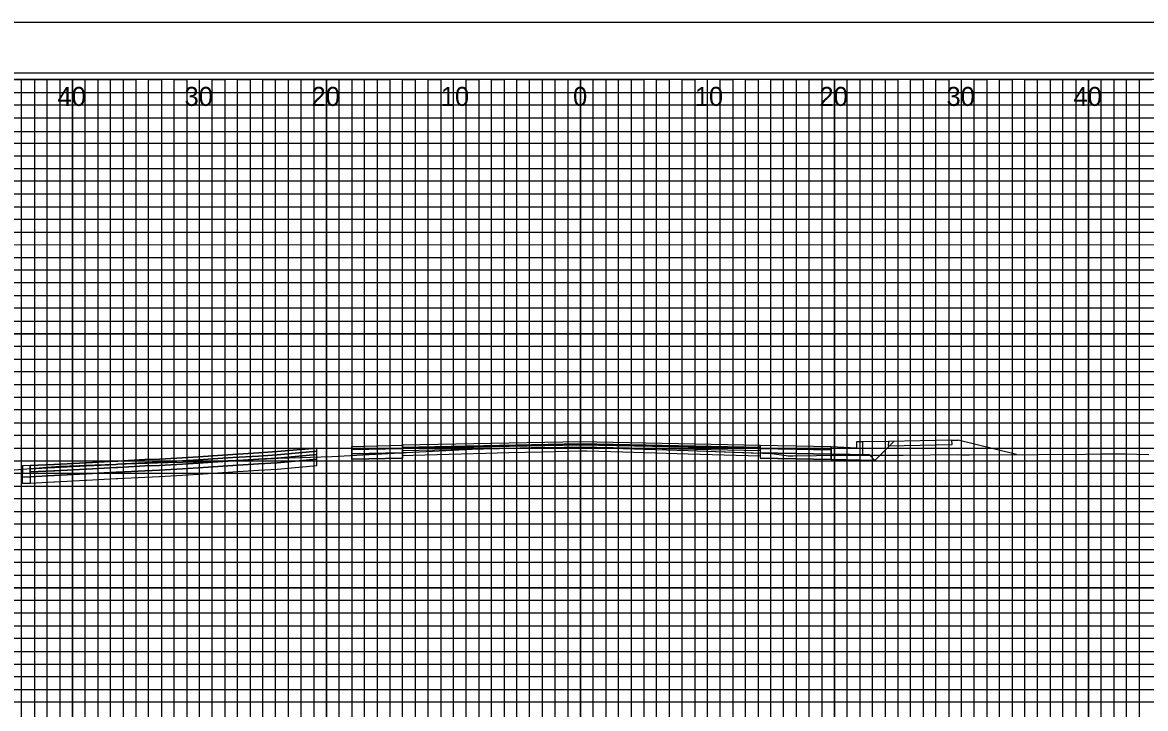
# Model space of a CAD drawing. Extents: x -13 to 760, y -5 to 1491.
# Drawn here: x 116.1 to 204.5, y 479.5 to 533.5 of the extents above; entities that cross this region are included whole.
import ezdxf

# ---------------------------------------------------------------- set-up
doc = ezdxf.new("R2010")
doc.units = 0
for name, color, linetype in [('Exist XS Ground Line', 7, 'Continuous'), ('Prop CMT Concrete Structures', 7, 'Continuous'), ('Prop CMT Pvmt Course 1', 7, 'Continuous'), ('Prop CMT Pvmt Course 2', 7, 'Continuous'), ('Prop CMT Pvmt Course 3', 7, 'Continuous'), ('Prop CMT Pvmt Course 4', 7, 'Continuous'), ('Prop CMT Subgrade Earthwork', 7, 'Continuous'), ('Prop Conc 4in Sidewalk', 7, 'Continuous'), ('Prop Conc Curb and Gutter', 7, 'Continuous'), ('Prop Corridor Mesh Bottom', 7, 'Continuous'), ('Prop XS Finish Grade', 7, 'Continuous'), ('Prop XS Offset Labels', 7, 'Continuous'), ('Scratch_Level_6', 7, 'Continuous'), ('Scratch_Level_9', 7, 'Continuous'), ('Sheet Cross Section CELL', 7, 'Continuous'), ('Sheet Cross Section Grid Major CELL', 7, 'Continuous'), ('Sheet Cross Section Grid Middle CELL', 7, 'Continuous'), ('Sheet Cross Section Grid Minor 1 CELL', 7, 'Continuous'), ('Sheet Cross Section Grid Minor 2 CELL', 7, 'Continuous'), ('Sheet Cutting Line CELL', 7, 'Continuous'), ('Sheet DOT Grid CELL', 7, 'Continuous'), ('Sheet Plot Border Inside CELL', 7, 'Continuous'), ('Sheet Plot Border Outside CELL', 7, 'Continuous')]:
    doc.layers.add(name, color=color, linetype=linetype)

msp = doc.modelspace()

# ---------------------------------------------------------------- linework, layer by layer
at = {"layer": 'Exist XS Ground Line'}
msp.add_lwpolyline([(113.131, 498.11), (119.011, 498.57), (120.529, 498.638), (120.932, 498.653), (127.534, 498.867), (129.822, 498.929), (135.896, 499.196), (136.221, 499.201), (140.42, 499.343), (146.795, 499.692), (152.539, 499.969), (154.375, 500.009), (156.989, 500.064), (160.509, 500.013), (163.351, 499.978), (168.488, 499.811), (175.072, 499.578), (176.205, 499.42), (176.368, 499.396), (176.443, 499.395), (176.534, 499.395), (176.638, 499.395), (176.755, 499.396), (180.424, 499.456), (180.483, 499.458), (180.574, 499.46), (180.672, 499.46), (184.748, 499.441), (184.767, 499.44), (184.78, 499.441), (184.803, 499.442), (184.825, 499.442), (185.421, 499.446), (189.682, 499.487), (189.989, 499.484), (190.316, 499.485), (190.651, 499.48), (196.06, 499.494), (199.761, 499.536), (200.967, 499.549), (202.882, 499.553), (204.751, 499.501)], dxfattribs=at)
msp.add_lwpolyline([(113.131, 498.11), (119.011, 498.57), (120.529, 498.638), (120.932, 498.653), (127.534, 498.867), (129.822, 498.929), (135.896, 499.196), (136.221, 499.201), (140.42, 499.343), (146.795, 499.692), (152.539, 499.969), (154.375, 500.009), (156.989, 500.064), (160.509, 500.013), (163.351, 499.978), (168.488, 499.811), (175.072, 499.578), (176.205, 499.42), (176.368, 499.396), (176.443, 499.395), (176.534, 499.395), (176.638, 499.395), (176.755, 499.396), (180.424, 499.456), (180.483, 499.458), (180.574, 499.46), (180.672, 499.46), (184.748, 499.441), (184.767, 499.44), (184.78, 499.441), (184.803, 499.442), (184.825, 499.442), (185.421, 499.446), (189.682, 499.487), (189.989, 499.484), (190.316, 499.485), (190.651, 499.48), (196.06, 499.494), (199.761, 499.536), (200.967, 499.549), (202.882, 499.553), (204.751, 499.501)], dxfattribs=at)
at = {"layer": 'Prop CMT Pvmt Course 1'}
for points in [[(116.661, 498.626), (116.661, 498.376), (118.533, 498.468), (118.583, 498.47), (121.046, 498.597), (121.118, 498.6), (123.444, 498.725), (123.587, 498.731), (125.701, 498.849), (126.847, 498.893), (129.114, 499.018), (132.635, 499.256), (134.648, 499.379), (136.124, 499.474), (139.246, 499.755), (139.246, 500.005), (136.124, 499.724), (134.648, 499.629), (132.635, 499.506), (129.114, 499.268), (126.847, 499.143), (125.701, 499.099), (123.587, 498.981), (123.444, 498.975), (121.118, 498.85), (121.046, 498.847), (118.583, 498.72), (118.533, 498.718), (116.661, 498.626)], [(142, 500.142), (146, 500.222), (146, 499.972), (146, 499.972), (142, 499.892), (142, 499.892), (142, 499.892), (142, 500.142), (142, 500.142)], [(146, 500.055), (146, 500.055), (146, 500.055), (160, 500.335), (160, 500.335), (174.143, 500.053), (174.143, 500.053), (174.143, 500.219), (160, 500.502), (160, 500.502), (146, 500.222), (146, 500.222), (146, 500.055)], [(174.143, 500.219), (174.143, 500.219), (174.143, 499.969), (174.143, 499.969), (174.143, 499.969), (179.75, 499.857), (179.75, 499.857), (179.75, 500.107), (174.143, 500.219)]]:
    msp.add_lwpolyline(points, dxfattribs=at)
at = {"layer": 'Prop CMT Pvmt Course 2'}
for points in [[(116.661, 498.376), (116.661, 498.126), (118.533, 498.218), (118.583, 498.22), (121.046, 498.347), (121.118, 498.35), (123.444, 498.475), (123.587, 498.481), (125.701, 498.599), (126.847, 498.643), (129.114, 498.768), (132.635, 499.006), (134.648, 499.129), (136.124, 499.224), (139.246, 499.505), (139.246, 499.755), (136.124, 499.474), (134.648, 499.379), (132.635, 499.256), (129.114, 499.018), (126.847, 498.893), (125.701, 498.849), (123.587, 498.731), (123.444, 498.725), (121.118, 498.6), (121.046, 498.597), (118.583, 498.47), (118.533, 498.468), (116.661, 498.376)], [(142, 499.892), (146, 499.972), (146, 499.639), (146, 499.639), (142, 499.559), (142, 499.559), (142, 499.559), (142, 499.892), (142, 499.892)], [(146, 499.993), (146, 499.993), (146, 499.993), (160, 500.273), (160, 500.273), (174.143, 499.99), (174.143, 499.99), (174.143, 500.053), (160, 500.335), (160, 500.335), (146, 500.055), (146, 500.055), (146, 499.993)], [(174.143, 499.969), (174.143, 499.969), (174.143, 499.636), (174.143, 499.636), (174.143, 499.636), (179.75, 499.524), (179.75, 499.524), (179.75, 499.857), (174.143, 499.969)]]:
    msp.add_lwpolyline(points, dxfattribs=at)
at = {"layer": 'Prop CMT Pvmt Course 3'}
for points in [[(146, 499.826), (146, 499.826), (146, 499.826), (160, 500.106), (160, 500.106), (174.143, 499.823), (174.143, 499.823), (174.143, 499.99), (160, 500.273), (160, 500.273), (146, 499.993), (146, 499.993), (146, 499.826)], [(116.661, 498.126), (116.661, 497.751), (118.533, 497.843), (118.583, 497.845), (121.046, 497.972), (121.118, 497.975), (123.444, 498.1), (123.587, 498.106), (125.701, 498.224), (126.847, 498.268), (129.114, 498.393), (132.635, 498.631), (134.648, 498.754), (136.124, 498.849), (139.246, 499.13), (139.246, 499.505), (136.124, 499.224), (134.648, 499.129), (132.635, 499.006), (129.114, 498.768), (126.847, 498.643), (125.701, 498.599), (123.587, 498.481), (123.444, 498.475), (121.118, 498.35), (121.046, 498.347), (118.583, 498.22), (118.533, 498.218), (116.661, 498.126)], [(142, 499.559), (146, 499.639), (146, 499.222), (146, 499.222), (142, 499.142), (142, 499.142), (142, 499.142), (142, 499.559), (142, 499.559)], [(174.143, 499.636), (174.143, 499.636), (174.143, 499.219), (174.143, 499.219), (174.143, 499.219), (179.75, 499.107), (179.75, 499.107), (179.75, 499.524), (174.143, 499.636)], [(179.75, 499.524), (179.75, 499.107), (183.176, 499.039), (182.751, 499.464), (179.75, 499.524)], [(116.065, 497.724), (116.065, 498.013), (116.085, 498.014), (116.661, 498.042), (116.661, 497.973), (116.661, 497.751), (116.083, 497.722), (116.065, 497.721), (116.065, 497.724)]]:
    msp.add_lwpolyline(points, dxfattribs=at)
at = {"layer": 'Prop CMT Pvmt Course 4'}
for points in [[(116.661, 497.751), (116.661, 497.251), (118.533, 497.343), (118.583, 497.345), (121.046, 497.472), (121.118, 497.475), (123.444, 497.6), (123.587, 497.606), (125.701, 497.724), (126.847, 497.768), (129.114, 497.893), (132.635, 498.131), (134.648, 498.254), (136.124, 498.349), (139.246, 498.63), (139.246, 499.13), (136.124, 498.849), (134.648, 498.754), (132.635, 498.631), (129.114, 498.393), (126.847, 498.268), (125.701, 498.224), (123.587, 498.106), (123.444, 498.1), (121.118, 497.975), (121.046, 497.972), (118.583, 497.845), (118.533, 497.843), (116.661, 497.751)], [(116.065, 497.225), (116.065, 497.721), (116.081, 497.722), (116.661, 497.751), (116.661, 497.631), (116.661, 497.251), (116.078, 497.222), (116.065, 497.221), (116.065, 497.225)]]:
    msp.add_lwpolyline(points, dxfattribs=at)
at = {"layer": 'Prop CMT Subgrade Earthwork'}
for points in [[(183.176, 499.039), (184.673, 500.536)], [(142, 499.142), (142, 499.142), (146, 499.222)], [(179.75, 499.107), (174.143, 499.219), (174.143, 499.219)], [(183.176, 499.039), (183.176, 499.039), (179.75, 499.107)], [(116.065, 497.221), (116.078, 497.222), (116.661, 497.251)]]:
    msp.add_lwpolyline(points, dxfattribs=at)
at = {"layer": 'Prop Conc 4in Sidewalk'}
msp.add_lwpolyline([(184.251, 500.527), (184.241, 500.194), (189.261, 500.294), (189.251, 500.627), (184.251, 500.527)], dxfattribs=at)
at = {"layer": 'Prop Conc Curb and Gutter'}
for points in [[(181.75, 499.987), (179.75, 500.107), (179.75, 499.524), (179.75, 499.524), (182.251, 499.474), (182.251, 499.474), (182.251, 499.474), (182.251, 500.487), (181.751, 500.487), (181.751, 500.487), (181.75, 499.987), (181.75, 499.987), (181.75, 499.987)], [(116.065, 498.02), (116.065, 498.013), (116.09, 498.014), (116.661, 498.042), (116.661, 498.486), (116.661, 498.626), (116.097, 498.597), (116.065, 498.595), (116.065, 498.02)]]:
    msp.add_lwpolyline(points, dxfattribs=at)
at = {"layer": 'Prop Corridor Mesh Bottom'}
for points in [[(160, 500.02), (160, 500.02), (160, 499.77), (160, 499.77), (160, 499.77), (156.989, 499.691), (156.989, 499.691), (156.989, 499.691), (154.375, 499.621), (154.375, 499.621), (152.539, 499.572), (146.795, 499.42), (146.795, 499.42), (146, 499.399), (146, 499.399), (146, 499.649), (146.795, 499.692), (146.795, 499.692), (152.539, 499.969), (154.375, 500.01), (154.375, 500.01), (156.989, 500.064), (156.989, 500.064), (156.989, 500.064), (160, 500.02)], [(174.143, 499.611), (174.143, 499.611), (174.143, 499.361), (174.143, 499.361), (174.143, 499.361), (168.488, 499.525), (168.488, 499.525), (163.351, 499.673), (160.509, 499.756), (160.509, 499.756), (160, 499.77), (160, 499.77), (160, 500.02), (160.509, 500.013), (160.509, 500.013), (163.351, 499.978), (168.488, 499.811), (168.488, 499.811), (174.143, 499.611)], [(179.75, 500.107), (179.75, 499.857)]]:
    msp.add_lwpolyline(points, dxfattribs=at)
at = {"layer": 'Prop XS Finish Grade'}
for points in [[(189.251, 500.627), (189.751, 500.637)], [(194.341, 499.49), (194.341, 499.49), (189.751, 500.637)], [(184.251, 500.527), (182.251, 500.487), (182.251, 500.487)]]:
    msp.add_lwpolyline(points, dxfattribs=at)
at = {"layer": 'Scratch_Level_6'}
msp.add_lwpolyline([(116.661, 498.626), (118.533, 498.718), (118.583, 498.72), (121.046, 498.847), (121.118, 498.85), (123.444, 498.975), (123.587, 498.981), (125.701, 499.099), (126.847, 499.143), (129.114, 499.268), (132.635, 499.506), (134.648, 499.629), (136.124, 499.724), (139.246, 500.005)], dxfattribs=at)
at = {"layer": 'Sheet Cross Section CELL'}
msp.add_lwpolyline([(320, 529.005), (0, 529.005), (0, 319.005), (320, 319.005)], close=True, dxfattribs=at)
at = {"layer": 'Sheet Cross Section Grid Major CELL'}
for p, q in [((130, 529.005), (120, 529.005)), ((120, 529.005), (120, 319.005)), ((130, 319.005), (130, 529.005)), ((150, 529.005), (140, 529.005)), ((140, 529.005), (140, 319.005)), ((150, 319.005), (150, 529.005)), ((170, 529.005), (160, 529.005)), ((160, 529.005), (160, 319.005)), ((170, 319.005), (170, 529.005)), ((190, 529.005), (180, 529.005)), ((180, 529.005), (180, 319.005)), ((190, 319.005), (190, 529.005)), ((210, 529.005), (200, 529.005)), ((200, 529.005), (200, 319.005))]:
    msp.add_line(p, q, dxfattribs=at)
for points in [[(0, 519.005), (320, 519.005), (320, 509.005), (0, 509.005)], [(0, 499.005), (320, 499.005), (320, 489.005), (0, 489.005)]]:
    msp.add_lwpolyline(points, dxfattribs=at)
at = {"layer": 'Sheet Cross Section Grid Middle CELL'}
for points in [[(115, 319.005), (115, 529.005), (125, 529.005), (125, 319.005)], [(135, 319.005), (135, 529.005), (145, 529.005), (145, 319.005)], [(155, 319.005), (155, 529.005), (165, 529.005), (165, 319.005)], [(175, 319.005), (175, 529.005), (185, 529.005), (185, 319.005)], [(195, 319.005), (195, 529.005), (205, 529.005)], [(0, 524.005), (275, 524.005)], [(0, 504.005), (320, 504.005), (320, 514.005), (0, 514.005)], [(0, 484.005), (320, 484.005), (320, 494.005), (0, 494.005)]]:
    msp.add_lwpolyline(points, dxfattribs=at)
at = {"layer": 'Sheet Cross Section Grid Minor 1 CELL'}
for p, q in [((0, 528.005), (260, 528.005)), ((260, 526.985), (0, 526.985)), ((0, 526.005), (260, 526.005)), ((260, 524.895), (0, 524.895)), ((0, 523.005), (320, 523.005))]:
    msp.add_line(p, q, dxfattribs=at)
for points in [[(0, 522.005), (270, 522.005), (320, 522.005), (320, 521.005), (0, 521.005)], [(0, 520.005), (320, 520.005), (320, 518.005), (0, 518.005)], [(0, 517.005), (320, 517.005), (320, 516.005), (0, 515.985)], [(0, 515.005), (320, 515.005), (320, 513.005), (0, 513.005)], [(0, 512.005), (320, 512.005), (320, 511.005), (0, 511.005)], [(0, 510.005), (320, 510.005), (320, 508.005), (0, 508.005)], [(0, 507.005), (320, 507.005), (320, 506.005), (0, 506.005)], [(0, 505.005), (320, 505.005), (320, 503.005), (0, 503.005)], [(0, 502.005), (320, 502.005), (320, 501.005), (0, 501.005)], [(0, 500.005), (320, 500.005), (320, 498.005), (0, 498.005)], [(0, 497.005), (320, 497.005), (320, 496.005), (0, 496.005)], [(0, 495.005), (320, 495.005), (320, 492.955), (320, 492.005), (320, 491.005), (0, 491.005)], [(0, 493.005), (320, 493.005), (320, 492.005), (0, 492.005)], [(0, 490.005), (320, 490.005), (320, 488.005), (0, 488.035)], [(0, 488.035), (320, 488.005), (320, 487.005), (0, 487.005)], [(0, 486.005), (320, 486.005), (320, 485.005), (0, 485.005)], [(0, 483.005), (320, 483.005), (320, 482.005), (0, 482.005)], [(0, 481.005), (320, 481.005), (320, 480.005), (0, 480.005)]]:
    msp.add_lwpolyline(points, dxfattribs=at)
at = {"layer": 'Sheet Cross Section Grid Minor 2 CELL'}
for points in [[(115, 319.005), (116, 319.005), (116, 529.005), (117, 529.005), (117, 319.005)], [(117, 319.005), (118, 319.005), (118, 529.005), (119, 529.005), (119, 319.005)], [(120, 319.005), (121, 319.005), (121, 529.005), (122, 529.005), (122, 319.005)], [(122, 319.005), (123, 319.005), (123, 529.005), (124, 529.005), (124, 319.005)], [(125, 319.005), (126, 319.005), (126, 529.005), (127, 529.005), (127, 319.005)], [(127, 319.005), (128, 319.005), (128, 529.005), (129, 529.005), (129, 319.005)], [(130, 319.005), (131, 319.005), (131, 529.005), (132, 529.005), (132, 319.005)], [(132, 319.005), (133, 319.005), (133, 529.005), (134, 529.005), (134, 319.005)], [(135, 319.005), (136, 319.005), (136, 529.005), (137, 529.005), (137, 319.005)], [(137, 319.005), (138, 319.005), (138, 529.005), (139, 529.005), (139, 319.005)], [(140, 319.005), (141, 319.005), (141, 529.005), (142, 529.005), (142, 319.005)], [(142, 319.005), (143, 319.005), (143, 529.005), (144, 529.005), (144, 319.005)], [(145, 319.005), (146, 319.005), (146, 529.005), (147, 529.005), (147, 319.005)], [(147, 319.005), (148, 319.005), (148, 529.005), (149, 529.005), (149, 319.005)], [(150, 319.005), (151, 319.005), (151, 529.005), (152, 529.005), (152, 319.005)], [(152, 319.005), (153, 319.005), (153, 529.005), (154, 529.005), (154, 319.005)], [(155, 319.005), (156, 319.005), (156, 529.005), (157, 529.005), (157, 319.005)], [(157, 319.005), (158, 319.005), (158, 529.005), (159, 529.005), (159, 319.005)], [(160, 319.005), (161, 319.005), (161, 529.005), (162, 529.005), (162, 319.005)], [(162, 319.005), (163, 319.005), (163, 529.005), (164, 529.005), (164, 319.005)], [(165, 319.005), (166, 319.005), (166, 529.005), (167, 529.005), (167, 319.005)], [(167, 319.005), (168, 319.005), (168, 529.005), (169, 529.005), (169, 319.005)], [(170, 319.005), (171, 319.005), (171, 529.005), (172, 529.005), (172, 319.005)], [(172, 319.005), (173, 319.005), (173, 529.005), (174, 529.005), (174, 319.005)], [(175, 319.005), (176, 319.005), (176, 529.005), (177, 529.005), (177, 319.005)], [(177, 319.005), (178, 319.005), (178, 529.005), (179, 529.005), (179, 319.005)], [(180, 319.005), (181, 319.005), (181, 529.005), (182, 529.005), (182, 319.005)], [(182, 319.005), (183, 319.005), (183, 529.005), (184, 529.005), (184, 319.005)], [(185, 319.005), (186, 319.005), (186, 529.005), (187, 529.005), (187, 319.005)], [(187, 319.005), (188, 319.005), (188, 529.005), (189, 529.005), (189, 319.005)], [(190, 319.005), (191, 319.005), (191, 529.005), (192, 529.005), (192, 319.005)], [(192, 319.005), (193, 319.005), (193, 529.005), (194, 529.005), (194, 319.005)], [(195, 319.005), (196, 319.005), (196, 529.005), (197, 529.005), (197, 319.005)], [(197, 319.005), (198, 319.005), (198, 529.005), (199, 529.005), (199, 319.005)], [(200, 319.005), (201, 319.005), (201, 529.005), (202, 529.005), (202, 319.005)], [(202, 319.005), (203, 319.005), (203, 529.005), (204, 529.005), (204, 319.005)]]:
    msp.add_lwpolyline(points, dxfattribs=at)
at = {"layer": 'Sheet Cutting Line CELL'}
msp.add_line((323.3, 533.505), (-13.4, 533.505), dxfattribs=at)
at = {"layer": 'Sheet DOT Grid CELL'}
for p, q in [((120, 319.005), (120, 529.005)), ((130, 319.005), (130, 529.005)), ((140, 319.005), (140, 529.005)), ((150, 319.005), (150, 529.005)), ((160, 319.005), (160, 529.005)), ((170, 319.005), (170, 529.005)), ((180, 319.005), (180, 529.005)), ((190, 319.005), (190, 529.005)), ((200, 319.005), (200, 529.005)), ((0, 519.005), (320, 519.005)), ((0, 509.005), (320, 509.005)), ((0, 499.005), (320, 499.005)), ((0, 489.005), (320, 489.005))]:
    msp.add_line(p, q, dxfattribs=at)
at = {"layer": 'Sheet Plot Border Inside CELL'}
msp.add_lwpolyline([(-10.8, 318.505), (322.4, 318.505), (322.4, 529.505), (-10.8, 529.505)], close=True, dxfattribs=at)
at = {"layer": 'Sheet Plot Border Outside CELL'}
msp.add_lwpolyline([(-13.4, 314.505), (323.3, 314.505), (323.3, 533.505), (-13.4, 533.505)], close=True, dxfattribs=at)

# ---------------------------------------------------------------- texts
at = {"layer": 'Prop CMT Concrete Structures'}
msp.add_text('X', height=0.0025, dxfattribs=at).set_placement((116.66, 498.624))
at = {"layer": 'Prop XS Offset Labels'}
for s, p in [('40', (118.828, 526.935)), ('30', (128.828, 526.935)), ('20', (138.828, 526.935)), ('10', (149.007, 526.935)), ('0', (159.421, 526.935)), ('0', (159.421, 526.935)), ('10', (169.007, 526.935)), ('20', (178.828, 526.935)), ('30', (188.828, 526.935)), ('40', (198.828, 526.935))]:
    msp.add_text(s, height=1.5, dxfattribs=at).set_placement(p)
at = {"layer": 'Scratch_Level_9'}
for p in [(189.25, 500.626), (141.999, 500.141), (159.999, 500.501), (179.749, 500.106), (179.749, 500.106), (181.749, 499.986), (184.25, 500.526), (194.34, 499.488)]:
    msp.add_text('X', height=0.0025, dxfattribs=at).set_placement(p)

doc.saveas('drawing.dxf')
